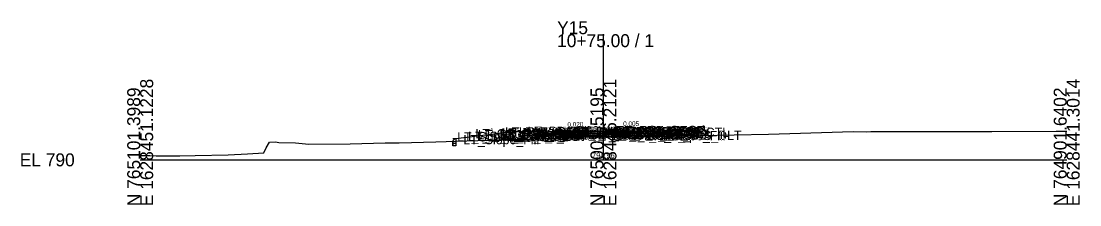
# Model space of a CAD drawing. Extents: x -26 to 203, y -10 to 2522.
# Drawn here: x -25.7 to 202.8, y 1490.3 to 1529.9 of the extents above; entities that cross this region are included whole.
import ezdxf

# ---------------------------------------------------------------- set-up
doc = ezdxf.new("R2010")
doc.units = 0
for name, color, linetype in [('Default', 7, 'Continuous'), ('Exist Cross Section Cell', 7, 'Continuous'), ('Exist XS Center Line Elevation Label', 7, 'Continuous'), ('Exist XS Ground Line', 7, 'Continuous'), ('Prop CMT Concrete Structures', 7, 'Continuous'), ('Prop CMT Pvmt Course 1', 7, 'Continuous'), ('Prop CMT Pvmt Course 1 Wedge', 7, 'Continuous'), ('Prop CMT Pvmt Course 2', 7, 'Continuous'), ('Prop CMT Pvmt Course 2 Wedge', 7, 'Continuous'), ('Prop CMT Pvmt Course 3', 7, 'Continuous'), ('Prop CMT Pvmt Course 3 Wedge', 7, 'Continuous'), ('Prop CMT Pvmt Surface', 7, 'Continuous'), ('Prop CMT Pvmt Surface Shoulder', 7, 'Continuous'), ('Prop CMT Pvmt Wedge Surface 2', 7, 'Continuous'), ('Prop CMT Pvmt Wedge Surface 3', 7, 'Continuous'), ('Prop CMT Shld Paved Course 1', 7, 'Continuous'), ('Prop CMT Shld Paved Course 2', 7, 'Continuous'), ('Prop CMT Shld Paved Course 3', 7, 'Continuous'), ('Prop CMT Slope Grass', 7, 'Continuous'), ('Prop CMT Subgrade Earthwork', 7, 'Continuous'), ('Prop XS Finish Grade CurbGutter', 7, 'Continuous'), ('Prop XS SE Text', 7, 'Continuous'), ('Prop XS Side Slope Text', 7, 'Continuous'), ('Scratch_Level_0', 7, 'Continuous')]:
    doc.layers.add(name, color=color, linetype=linetype)

msp = doc.modelspace()

# ---------------------------------------------------------------- linework, layer by layer
at = {"layer": 'Exist Cross Section Cell'}
for p, q in [((100, 1500), (100, 1527.1)), ((0, 1500), (100, 1500)), ((100, 1500), (200, 1500))]:
    msp.add_line(p, q, dxfattribs=at)
at = {"layer": 'Exist XS Ground Line'}
msp.add_lwpolyline([(0, 1500.94), (2.07, 1500.91), (3.46, 1500.89), (8.58, 1500.9), (11.84, 1500.93), (18.97, 1501.05), (23.17, 1501.28), (26.66, 1501.53), (27.23, 1502.57), (27.9, 1503.79), (29.22, 1503.86), (29.94, 1503.77), (33.52, 1503.65), (36.44, 1503.41), (45.32, 1503.48), (52.89, 1503.64), (55.88, 1503.69), (63.8, 1503.88), (70.5, 1504.11), (82.26, 1504.46), (87.58, 1504.6), (91.37, 1504.73), (92.21, 1504.8), (93.76, 1504.95), (100, 1504.96), (105.38, 1504.97), (105.95, 1504.97), (106.85, 1504.99), (112.52, 1505.03), (117.39, 1505.19), (120.8, 1505.27), (135.6, 1505.56), (140.27, 1505.68), (153.93, 1506.09), (156.75, 1506.07), (157.71, 1506.09), (158.06, 1506.09), (182.64, 1506.11), (183.88, 1506.12), (197.7, 1506.17), (198.7, 1506.17), (199.66, 1506.18), (200, 1506.18)], dxfattribs=at)
at = {"layer": 'Prop CMT Concrete Structures'}
for points in [[(114, 1506.33), (114, 1505.74), (112, 1505.74)], [(112, 1506.33), (113, 1506.24), (114, 1506.33)], [(112, 1505.74), (112, 1506.33)], [(86, 1506.03), (86, 1505.44), (88, 1505.44)], [(88, 1506.03), (87, 1505.94), (86, 1506.03)], [(88, 1505.44), (88, 1506.03)]]:
    msp.add_lwpolyline(points, dxfattribs=at)
at = {"layer": 'Prop CMT Pvmt Course 1'}
for points in [[(100, 1506.27), (88, 1506.03)], [(100, 1506.27), (93.76, 1506.14)], [(100, 1506.27), (112, 1506.33)], [(100, 1506.27), (105.95, 1506.3)], [(100, 1506.14), (100, 1506.27)], [(100, 1506.02), (100, 1506.27)], [(100, 1506.14), (100, 1506.27)], [(100, 1506.02), (100, 1506.27)], [(112, 1506.08), (100, 1506.02)], [(112, 1506.33), (112, 1506.08)], [(88, 1506.03), (88, 1505.78)], [(88, 1505.78), (100, 1506.02)]]:
    msp.add_lwpolyline(points, dxfattribs=at)
at = {"layer": 'Prop CMT Pvmt Course 1 Wedge'}
for points in [[(100, 1506.14), (100, 1506.02)], [(100, 1506.02), (100, 1506.14)], [(105.95, 1506.05), (105.38, 1506.04), (100, 1506.02)], [(100, 1506.02), (93.76, 1505.89)]]:
    msp.add_lwpolyline(points, dxfattribs=at)
at = {"layer": 'Prop CMT Pvmt Course 2'}
for points in [[(100, 1506.02), (112, 1506.08)], [(112, 1506.08), (112, 1505.74)], [(100, 1506.02), (88, 1505.78)], [(88, 1505.78), (88, 1505.44)], [(88, 1505.44), (100, 1505.68)], [(100, 1505.68), (100, 1506.02)], [(100, 1505.68), (100, 1506.02)], [(112, 1505.74), (100, 1505.68)]]:
    msp.add_lwpolyline(points, dxfattribs=at)
at = {"layer": 'Prop CMT Pvmt Course 2 Wedge'}
for points in [[(100, 1506.02), (105.38, 1506.04), (105.95, 1506.05)], [(93.76, 1505.89), (100, 1506.02)], [(100, 1505.68), (93.76, 1505.56)], [(100, 1506.02), (100, 1505.68)], [(100, 1505.68), (100, 1506.02)], [(105.95, 1505.71), (105.38, 1505.71), (100, 1505.68)]]:
    msp.add_lwpolyline(points, dxfattribs=at)
at = {"layer": 'Prop CMT Pvmt Course 3'}
msp.add_line((114, 1505.74), (114.5, 1505.74), dxfattribs=at)
for points in [[(100, 1505.68), (88, 1505.44)], [(88, 1505.44), (88, 1505.11)], [(88, 1505.11), (100, 1505.35)], [(100, 1505.68), (112, 1505.74)], [(100, 1505.35), (100, 1505.68)], [(100, 1505.35), (100, 1505.68)], [(112, 1505.41), (100, 1505.35)], [(112, 1505.74), (112, 1505.41)]]:
    msp.add_lwpolyline(points, dxfattribs=at)
at = {"layer": 'Prop CMT Pvmt Course 3 Wedge'}
for points in [[(93.76, 1505.56), (100, 1505.68)], [(100, 1504.96), (93.76, 1504.95)], [(100, 1505.68), (105.38, 1505.71), (105.95, 1505.71)], [(100, 1505.68), (100, 1504.96)], [(100, 1504.96), (100, 1505.68)], [(105.95, 1504.97), (105.38, 1504.97), (100, 1504.96)]]:
    msp.add_lwpolyline(points, dxfattribs=at)
at = {"layer": 'Prop CMT Pvmt Surface'}
for points in [[(100, 1506.27), (88, 1506.03)], [(100, 1506.27), (93.76, 1506.14)], [(100, 1506.27), (112, 1506.33)], [(100, 1506.27), (105.95, 1506.3)]]:
    msp.add_lwpolyline(points, dxfattribs=at)
at = {"layer": 'Prop CMT Pvmt Surface Shoulder'}
for points in [[(112, 1506.33), (112, 1506.33)], [(88, 1506.03), (88, 1506.03)]]:
    msp.add_lwpolyline(points, dxfattribs=at)
at = {"layer": 'Prop CMT Pvmt Wedge Surface 2'}
for points in [[(100, 1506.02), (100, 1506.27)], [(100, 1506.02), (100, 1506.27)], [(100, 1506.02), (100, 1506.27)], [(100, 1506.02), (100, 1506.27)], [(100, 1506.02), (105.95, 1506.05)], [(100, 1506.02), (93.76, 1505.89)]]:
    msp.add_lwpolyline(points, dxfattribs=at)
at = {"layer": 'Prop CMT Pvmt Wedge Surface 3'}
for points in [[(100, 1505.68), (100, 1506.27)], [(100, 1505.68), (100, 1506.27)], [(100, 1505.68), (100, 1506.27)], [(100, 1505.68), (100, 1506.27)], [(100, 1505.68), (93.76, 1505.56)], [(100, 1505.68), (105.95, 1505.71)]]:
    msp.add_lwpolyline(points, dxfattribs=at)
at = {"layer": 'Prop CMT Shld Paved Course 1'}
for points in [[(112, 1506.33), (112, 1506.33)], [(112, 1506.08), (112, 1506.33)], [(88, 1506.03), (88, 1506.03)], [(88, 1505.78), (88, 1506.03)]]:
    msp.add_lwpolyline(points, dxfattribs=at)
at = {"layer": 'Prop CMT Shld Paved Course 2'}
for p, q in [((86, 1505.44), (88, 1505.44)), ((114, 1505.74), (112, 1505.74))]:
    msp.add_line(p, q, dxfattribs=at)
for points in [[(112, 1505.74), (112, 1506.08)], [(88, 1505.44), (88, 1505.78)]]:
    msp.add_lwpolyline(points, dxfattribs=at)
at = {"layer": 'Prop CMT Shld Paved Course 3'}
for p, q in [((85.16, 1505.1), (88, 1505.11)), ((114.84, 1505.4), (112, 1505.41))]:
    msp.add_line(p, q, dxfattribs=at)
for points in [[(88, 1505.44), (86, 1505.44), (85.5, 1505.44), (85.16, 1505.1)], [(88, 1505.11), (88, 1505.44)], [(112, 1505.41), (112, 1505.74)], [(112, 1505.74), (114.5, 1505.74), (114.5, 1505.74), (114.84, 1505.4)]]:
    msp.add_lwpolyline(points, dxfattribs=at)
at = {"layer": 'Prop CMT Slope Grass'}
for p, q in [((81, 1506.13), (68.13, 1504.51)), ((86, 1506.03), (81, 1506.13))]:
    msp.add_line(p, q, dxfattribs=at)
for points in [[(114, 1506.33), (119, 1506.43), (122.38, 1505.3)], [(68.13, 1504.51), (68.13, 1503.01), (67.46, 1503.01), (67.46, 1504.01)]]:
    msp.add_lwpolyline(points, dxfattribs=at)
at = {"layer": 'Prop CMT Subgrade Earthwork'}
for p, q in [((85.16, 1505.1), (84.2, 1506.06)), ((114.84, 1505.4), (115.8, 1506.36)), ((88, 1505.11), (85.16, 1505.1)), ((112, 1505.41), (114.84, 1505.4))]:
    msp.add_line(p, q, dxfattribs=at)
for points in [[(100, 1505.35), (88, 1505.11)], [(100, 1505.35), (112, 1505.41)]]:
    msp.add_lwpolyline(points, dxfattribs=at)
at = {"layer": 'Prop XS Finish Grade CurbGutter'}
for p, q in [((68.13, 1504.51), (67.46, 1504.51)), ((67.46, 1504.09), (67.82, 1504.46)), ((67.46, 1504.09), (67.46, 1503.51)), ((67.46, 1504.01), (67.46, 1504.01)), ((68.13, 1504.51), (67.94, 1504.51)), ((68.13, 1504.51), (68.13, 1503.51)), ((67.46, 1503.51), (67.46, 1503.01)), ((68.13, 1503.51), (67.46, 1503.51)), ((68.13, 1503.01), (67.46, 1503.01)), ((68.13, 1503.51), (68.13, 1503.01))]:
    msp.add_line(p, q, dxfattribs=at)
msp.add_arc((67.94, 1504.34), 0.166, 90, 136.0003, dxfattribs=at)

# ---------------------------------------------------------------- texts
at = {"layer": 'Default'}
msp.add_text('-', height=0.0001, dxfattribs=at).set_placement((0, 1500))
at = {"layer": 'Exist Cross Section Cell'}
for s, p in [('Y15', (90, 1527.1)), ('10+75.00 / 1', (90, 1524.3)), ('EL 790', (-26, 1498.6))]:
    msp.add_text(s, height=2.8, dxfattribs=at).set_placement(p)
for s, p in [('N 765101.3989', (0, 1490)), ('E 1628451.1228', (2.8, 1490)), ('N 765001.5195', (100, 1490)), ('E 1628446.2121', (102.8, 1490)), ('N 764901.6402', (200, 1490)), ('E 1628441.3014', (202.8, 1490))]:
    msp.add_text(s, height=2.8, rotation=90, dxfattribs=at).set_placement(p)
at = {"layer": 'Exist XS Center Line Elevation Label'}
msp.add_text('794.96', height=1.2, dxfattribs=at).set_placement((97.53, 1500.36))
at = {"layer": 'Prop XS SE Text'}
for s, rotation, p in [('0.020', 1.1458, (92.23, 1507.11)), ('0.005', 0.2865, (104.26, 1507.29))]:
    msp.add_text(s, height=1, rotation=rotation, dxfattribs=at).set_placement(p)
at = {"layer": 'Prop XS Side Slope Text'}
for s, rotation, p in [('8:1', 7.1721, (74.51, 1505.63)), ('3:1', 341.5651, (121.02, 1506.57))]:
    msp.add_text(s, height=1, rotation=rotation, dxfattribs=at).set_placement(p)
at = {"layer": 'Scratch_Level_0'}
for s, p in [('LT_Sub_OSS_DLT', (68.43, 1503.97)), ('LT_Sub_Trench_Out', (70.77, 1504.08)), ('LT_GS_OS_CTL', (72.37, 1504.63)), ('LT_PS3_Shelf_Out', (72.89, 1504.42)), ('LT_PS3_OEOP', (77.64, 1504.43)), ('LT_PS2_OEOP', (77.98, 1504.77)), ('LT_Sub_OEOT', (78.08, 1504.11)), ('LT_PV2_OEOT', (78.17, 1504.78)), ('LT_PV3_OEOT', (78.17, 1504.44)), ('LT_PV1_OEOT', (78.74, 1505.03)), ('LT_PS1_OEOP', (78.8, 1505.03)), ('LT_PV2_OEEOP_W', (81.18, 1504.89)), ('LT_PV3_OEEOP_W', (81.18, 1504.56)), ('LT_PV1_OEEOP_W', (81.74, 1505.02)), ('LT_PV1_OEEOP', (83.63, 1505.14)), ('RT_PV1_PGL_W', (89.84, 1505.14)), ('LT_PV1_PGL_W', (89.89, 1505.14)), ('RT_PV2_OEEOP_W', (93.32, 1505.05)), ('RT_PV3_OEEOP_W', (93.32, 1504.71)), ('Sub_PGL', (93.81, 1504.35)), ('RT_PV1_OEEOP_W', (93.89, 1505.17)), ('PV2_PGL', (93.91, 1505.02)), ('PV3_PGL', (93.91, 1504.68)), ('PV1_PGL', (94.47, 1505.27)), ('RT_PV1_OEEOP', (95.78, 1505.3)), ('RT_Sub_Trench_Out', (97.59, 1504.38)), ('RT_PS3_Shelf_Out', (99.03, 1504.72)), ('RT_Sub_OEOT', (102.03, 1504.41)), ('RT_PV2_OEOT', (102.13, 1505.08)), ('RT_PV3_OEOT', (102.13, 1504.74)), ('RT_PS2_OEOP', (102.44, 1505.07)), ('RT_PV1_OEOT', (102.69, 1505.33)), ('RT_PS1_OEOP', (102.76, 1505.33)), ('RT_PS3_OEOP', (102.78, 1504.73)), ('RT_GS_OS_CTL', (106.32, 1504.93)), ('RT_Sub_OSS_DLT', (106.32, 1504.27)), ('RT_Slope_Fill', (109.56, 1504.23)), ('LT_Slope_Fill', (69.76, 1503.37))]:
    msp.add_text(s, height=2, dxfattribs=at).set_placement(p)

doc.saveas('drawing.dxf')
